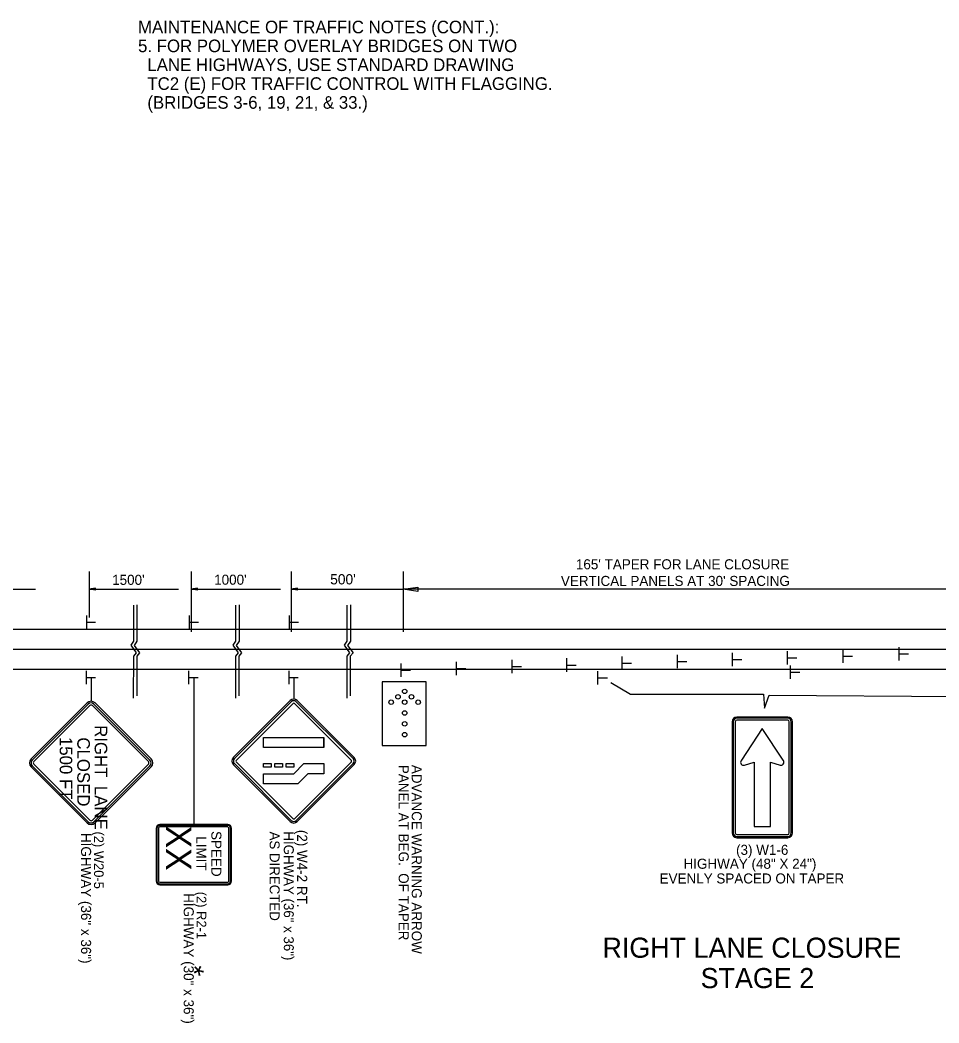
# Model space of a CAD drawing. Extents: x 1930579 to 1937521, y 596183 to 597599.
# Drawn here: x 1935656 to 1936204, y 596928 to 597526 of the extents above; entities that cross this region are included whole.
import ezdxf

# ---------------------------------------------------------------- set-up
doc = ezdxf.new("R2010")
doc.units = 0
for name, color, linetype in [('Default', 7, 'Continuous'), ('P_TC_Signs_Permanent', 7, 'Continuous'), ('P_TC_Signs_Temporary', 7, 'Continuous'), ('R_Annotation', 7, 'Continuous')]:
    doc.layers.add(name, color=color, linetype=linetype)

msp = doc.modelspace()

# ---------------------------------------------------------------- linework, layer by layer
at = {"layer": 'Default'}
for p, q in [((1935696.74, 597197.04), (1935696.74, 597169.66)), ((1935757.62, 597197.04), (1935757.62, 597161.13)), ((1935817.31, 597197.04), (1935817.31, 597161.13)), ((1935884.09, 597197.04), (1935884.09, 597161.13)), ((1935611.55, 597186.51), (1935664.78, 597186.51)), ((1935700.57, 597187.09), (1935696.74, 597186.51)), ((1935696.74, 597186.51), (1935749.97, 597186.51)), ((1935700.57, 597185.94), (1935696.74, 597186.51)), ((1935700.57, 597186.99), (1935697.38, 597186.51)), ((1935700.57, 597186.03), (1935697.38, 597186.51)), ((1935700.57, 597186.89), (1935698.04, 597186.51)), ((1935700.57, 597186.13), (1935698.04, 597186.51)), ((1935700.57, 597186.8), (1935698.67, 597186.51)), ((1935700.57, 597186.23), (1935698.67, 597186.51)), ((1935700.57, 597186.7), (1935699.32, 597186.51)), ((1935700.57, 597186.33), (1935699.32, 597186.51)), ((1935700.57, 597186.6), (1935699.96, 597186.51)), ((1935700.57, 597186.42), (1935699.96, 597186.51)), ((1935700.57, 597185.94), (1935700.57, 597187.09)), ((1935761.45, 597187.09), (1935757.62, 597186.51)), ((1935757.62, 597186.51), (1935810.86, 597186.51)), ((1935761.45, 597185.94), (1935757.62, 597186.51)), ((1935761.45, 597186.99), (1935758.26, 597186.51)), ((1935761.45, 597186.03), (1935758.26, 597186.51)), ((1935761.45, 597186.89), (1935758.92, 597186.51)), ((1935761.45, 597186.13), (1935758.92, 597186.51)), ((1935761.45, 597186.8), (1935759.56, 597186.51)), ((1935761.45, 597186.23), (1935759.56, 597186.51)), ((1935761.45, 597186.7), (1935760.21, 597186.51)), ((1935761.45, 597186.33), (1935760.21, 597186.51)), ((1935761.45, 597186.6), (1935760.85, 597186.51)), ((1935761.45, 597186.42), (1935760.85, 597186.51)), ((1935761.45, 597185.94), (1935761.45, 597187.09)), ((1935821.13, 597187.09), (1935817.31, 597186.51)), ((1935817.31, 597186.51), (1935884.09, 597186.51)), ((1935821.13, 597185.94), (1935817.31, 597186.51)), ((1935821.13, 597186.99), (1935817.95, 597186.51)), ((1935821.13, 597186.03), (1935817.95, 597186.51)), ((1935821.13, 597186.89), (1935818.6, 597186.51)), ((1935821.13, 597186.13), (1935818.6, 597186.51)), ((1935821.13, 597186.8), (1935819.24, 597186.51)), ((1935821.13, 597186.23), (1935819.24, 597186.51)), ((1935821.13, 597186.7), (1935819.89, 597186.51)), ((1935821.13, 597186.33), (1935819.89, 597186.51)), ((1935821.13, 597186.6), (1935820.53, 597186.51)), ((1935821.13, 597186.42), (1935820.53, 597186.51)), ((1935821.13, 597185.94), (1935821.13, 597187.09)), ((1935884.09, 597186.51), (1935892.95, 597187.84)), ((1936251.3, 597186.51), (1935884.09, 597186.51)), ((1935892.95, 597185.18), (1935884.09, 597186.51)), ((1935892.95, 597187.84), (1935892.95, 597185.18)), ((1935695.06, 597170.87), (1935695.06, 597162.89)), ((1935695.18, 597166.9), (1935700.62, 597166.9)), ((1935756.34, 597170.87), (1935756.34, 597162.89)), ((1935756.46, 597166.9), (1935761.9, 597166.9)), ((1935816.02, 597170.87), (1935816.02, 597162.89)), ((1935816.13, 597166.9), (1935821.58, 597166.9)), ((1936503.04, 597162.55), (1935188.53, 597162.55)), ((1936503.04, 597150.55), (1935188.53, 597150.55)), ((1936080.66, 597140.66), (1936080.66, 597148.64)), ((1936113.5, 597141.57), (1936113.5, 597149.55)), ((1936146.65, 597142.67), (1936146.65, 597150.65)), ((1936180.12, 597143.96), (1936180.12, 597151.94)), ((1935915.88, 597135.25), (1935915.88, 597143.23)), ((1935949.18, 597136.49), (1935949.18, 597144.46)), ((1935981.84, 597137.34), (1935981.84, 597145.32)), ((1936014.83, 597138.38), (1936014.83, 597146.36)), ((1936047.81, 597139.43), (1936047.81, 597147.41)), ((1936047.93, 597143.4), (1936053.38, 597143.4)), ((1936080.78, 597144.63), (1936086.23, 597144.63)), ((1936113.61, 597145.53), (1936119.06, 597145.53)), ((1936146.77, 597146.64), (1936152.21, 597146.64)), ((1936180.24, 597147.93), (1936185.69, 597147.93)), ((1936503.04, 597138.55), (1935188.53, 597138.55)), ((1935695.06, 597129.89), (1935695.06, 597137.87)), ((1935756.31, 597129.89), (1935756.31, 597137.87)), ((1935816, 597129.89), (1935816, 597137.87)), ((1935882.89, 597134.21), (1935882.89, 597142.18)), ((1935883.01, 597138.17), (1935888.46, 597138.17)), ((1935915.99, 597139.22), (1935921.44, 597139.22)), ((1935949.3, 597140.45), (1935954.75, 597140.45)), ((1935981.96, 597141.31), (1935987.41, 597141.31)), ((1936000.39, 597129.61), (1936000.39, 597137.59)), ((1936014.94, 597142.35), (1936020.39, 597142.35)), ((1936115.35, 597133.1), (1936115.35, 597141.08)), ((1936115.47, 597137.07), (1936120.92, 597137.07)), ((1935695.17, 597133.86), (1935700.62, 597133.86)), ((1935756.43, 597133.86), (1935761.87, 597133.86)), ((1935816.11, 597133.86), (1935821.56, 597133.86)), ((1936000.51, 597133.58), (1936005.96, 597133.58))]:
    msp.add_line(p, q, dxfattribs=at)
for points in [[(1935723.24, 597177.07), (1935723.24, 597155.55), (1935721.58, 597153.08), (1935724.81, 597148.65), (1935723.11, 597146.6), (1935723.1, 597121.58)], [(1935725.28, 597177.27), (1935725.28, 597155.46), (1935723.62, 597152.99), (1935726.86, 597148.56), (1935725.15, 597146.52), (1935725.15, 597123.02)], [(1935784.12, 597177.07), (1935784.12, 597155.55), (1935782.46, 597153.08), (1935785.7, 597148.65), (1935783.99, 597146.6), (1935783.99, 597121.58)], [(1935786.17, 597177.27), (1935786.17, 597155.46), (1935784.5, 597152.99), (1935787.74, 597148.56), (1935786.04, 597146.52), (1935786.03, 597123.02)], [(1935850.58, 597177.07), (1935850.58, 597155.55), (1935848.92, 597153.08), (1935852.15, 597148.65), (1935850.45, 597146.6), (1935850.44, 597121.58)], [(1935852.62, 597177.27), (1935852.62, 597155.46), (1935850.96, 597152.99), (1935854.2, 597148.56), (1935852.49, 597146.52), (1935852.49, 597123.02)]]:
    msp.add_lwpolyline(points, dxfattribs=at)
msp.add_lwpolyline([(1935871.59, 597131.26), (1935871.59, 597093.28), (1935897.86, 597093.28), (1935897.86, 597131.26)], close=True, dxfattribs=at)
for centre in [(1935885.02, 597125.57), (1935876.97, 597119.12), (1935881, 597122.35), (1935885.02, 597119.12), (1935889.05, 597122.35), (1935893.07, 597119.12), (1935885.02, 597112.67), (1935885.02, 597106.22), (1935885.02, 597099.77)]:
    msp.add_circle(centre, 1.34, dxfattribs=at)
at = {"layer": 'P_TC_Signs_Permanent'}
for p, q in [((1935782.77, 597086.11), (1935816.72, 597120.05)), ((1936080.4, 597107.48), (1936080.4, 597041.1)), ((1936081.15, 597107.48), (1936081.15, 597041.1)), ((1936082.27, 597107.48), (1936082.27, 597041.1)), ((1936113.59, 597110.29), (1936083.21, 597110.29)), ((1936113.59, 597109.54), (1936083.21, 597109.54)), ((1936113.59, 597108.41), (1936083.21, 597108.41)), ((1936114.52, 597041.1), (1936114.52, 597107.48)), ((1936115.65, 597041.1), (1936115.65, 597107.48)), ((1936116.4, 597041.1), (1936116.4, 597107.48)), ((1935836.84, 597092.03), (1935836.84, 597098.03)), ((1935816.72, 597047.93), (1935782.77, 597081.87)), ((1935854.9, 597081.87), (1935820.96, 597047.93)), ((1935736.65, 597043.94), (1935736.65, 597012.44)), ((1935737.21, 597043.94), (1935737.21, 597012.44)), ((1935738.15, 597043.94), (1935738.15, 597012.44)), ((1935779.4, 597046.19), (1935738.9, 597046.19)), ((1935779.4, 597045.63), (1935738.9, 597045.63)), ((1935779.4, 597044.69), (1935738.9, 597044.69)), ((1935780.15, 597012.44), (1935780.15, 597043.94)), ((1935781.09, 597012.44), (1935781.09, 597043.94)), ((1935781.65, 597012.44), (1935781.65, 597043.94)), ((1936083.21, 597040.16), (1936113.59, 597040.16)), ((1936083.21, 597039.04), (1936113.59, 597039.04)), ((1936083.21, 597038.29), (1936113.59, 597038.29)), ((1935738.9, 597011.69), (1935779.4, 597011.69)), ((1935738.9, 597010.75), (1935779.4, 597010.75)), ((1935738.9, 597010.19), (1935779.4, 597010.19))]:
    msp.add_line(p, q, dxfattribs=at)
for points in [[(1935817.35, 597119.42), (1935783.41, 597085.47)], [(1935854.26, 597085.47), (1935820.32, 597119.42)], [(1935820.96, 597120.05), (1935837.93, 597103.08), (1935854.9, 597086.11)], [(1935784.47, 597084.41), (1935818.41, 597118.35)], [(1935819.26, 597118.35), (1935853.2, 597084.41)], [(1936110.84, 597084.55), (1936098.4, 597103.54), (1936085.99, 597084.54)], [(1935818.41, 597049.62), (1935784.47, 597083.56)], [(1935853.2, 597083.56), (1935819.26, 597049.62)], [(1936087.76, 597081.59), (1936093.52, 597083.31), (1936093.52, 597045.04), (1936103.27, 597045.04), (1936103.27, 597083.31), (1936109.02, 597081.55)], [(1935783.41, 597082.5), (1935817.35, 597048.56)], [(1935820.32, 597048.56), (1935854.26, 597082.5)]]:
    msp.add_lwpolyline(points, dxfattribs=at)
for points in [[(1935800.84, 597092.03), (1935800.84, 597098.03), (1935836.84, 597098.03), (1935836.84, 597092.03)], [(1935800.84, 597080.39), (1935800.84, 597082.49), (1935805.34, 597082.49), (1935805.34, 597080.39)], [(1935800.84, 597070.49), (1935800.84, 597076.49), (1935818.84, 597076.49), (1935824.84, 597082.49), (1935836.84, 597082.49), (1935836.84, 597076.49), (1935827.32, 597076.49), (1935821.32, 597070.49)], [(1935807.59, 597080.39), (1935807.59, 597082.49), (1935812.09, 597082.49), (1935812.09, 597080.39)], [(1935814.34, 597080.39), (1935814.34, 597082.49), (1935818.84, 597082.49), (1935818.84, 597080.39)]]:
    msp.add_lwpolyline(points, close=True, dxfattribs=at)
for centre, radius, start, end in [((1935818.84, 597117.93), 3, 45, 135), ((1935818.84, 597117.93), 2.1, 45, 135), ((1935818.84, 597117.93), 0.6, 45, 135), ((1936083.21, 597107.48), 2.81, 90, 180), ((1936083.21, 597107.48), 2.06, 90, 180), ((1936083.21, 597107.48), 0.938, 90, 180), ((1936113.59, 597107.48), 2.81, 360, 90), ((1936113.59, 597107.48), 2.06, 360, 90), ((1936113.59, 597107.48), 0.938, 360, 90), ((1935784.9, 597083.99), 3, 135, 225), ((1935784.9, 597083.99), 2.1, 135, 225), ((1935784.9, 597083.99), 0.6, 135, 225), ((1935852.78, 597083.99), 0.6, 315, 45), ((1935852.78, 597083.99), 2.1, 315, 45), ((1935852.78, 597083.99), 3, 315, 45), ((1936087.28, 597083.28), 1.76, 146.59943, 285.96908), ((1936023.19, 597125.54), 75, 326.59943, 326.85697), ((1936109.52, 597083.28), 1.8, 254.03093, 33.47548), ((1936173.58, 597125.64), 75, 213.2286, 213.47548), ((1935818.84, 597050.05), 3, 225, 315), ((1935818.84, 597050.05), 2.1, 225, 315), ((1935818.84, 597050.05), 0.6, 225, 315), ((1935738.9, 597043.94), 2.25, 90, 180), ((1935738.9, 597043.94), 1.69, 90, 180), ((1935738.9, 597043.94), 0.75, 90, 180), ((1935779.4, 597043.94), 2.25, 360, 90), ((1935779.4, 597043.94), 1.69, 360, 90), ((1935779.4, 597043.94), 0.75, 360, 90), ((1936083.21, 597041.1), 2.81, 180, 270), ((1936083.21, 597041.1), 2.06, 180, 270), ((1936083.21, 597041.1), 0.937, 180, 270), ((1936113.59, 597041.1), 2.81, 270, 360), ((1936113.59, 597041.1), 2.06, 270, 360), ((1936113.59, 597041.1), 0.938, 270, 360), ((1935738.9, 597012.44), 2.25, 180, 270), ((1935738.9, 597012.44), 1.69, 180, 270), ((1935738.9, 597012.44), 0.75, 180, 270), ((1935779.4, 597012.44), 2.25, 270, 360), ((1935779.4, 597012.44), 1.69, 270, 360), ((1935779.4, 597012.44), 0.75, 270, 360)]:
    msp.add_arc(centre, radius, start, end, dxfattribs=at)
at = {"layer": 'P_TC_Signs_Temporary'}
for p, q in [((1935662.1, 597085.29), (1935695.51, 597118.71)), ((1935700.28, 597118.71), (1935733.7, 597085.29)), ((1935662.76, 597084.63), (1935696.17, 597118.04)), ((1935663.69, 597083.7), (1935697.1, 597117.11)), ((1935698.69, 597117.11), (1935732.1, 597083.7)), ((1935699.62, 597118.04), (1935733.03, 597084.63)), ((1935695.51, 597047.11), (1935662.1, 597080.52)), ((1935696.17, 597047.77), (1935662.76, 597081.18)), ((1935697.1, 597048.7), (1935663.69, 597082.11)), ((1935732.1, 597082.11), (1935698.69, 597048.7)), ((1935733.03, 597081.18), (1935699.62, 597047.77)), ((1935733.7, 597080.52), (1935700.28, 597047.11))]:
    msp.add_line(p, q, dxfattribs=at)
for centre, radius, start, end in [((1935697.9, 597116.32), 3.37, 45, 135), ((1935697.9, 597116.32), 2.44, 45, 135), ((1935697.9, 597116.32), 1.12, 45, 135), ((1935664.49, 597082.91), 3.37, 135, 225), ((1935664.49, 597082.91), 2.44, 135, 225), ((1935664.49, 597082.91), 1.13, 135, 225), ((1935731.31, 597082.91), 1.13, 315, 45), ((1935731.31, 597082.91), 2.44, 315, 45), ((1935731.31, 597082.91), 3.38, 315, 45), ((1935697.9, 597049.5), 3.38, 225, 315), ((1935697.9, 597049.5), 2.44, 225, 315), ((1935697.9, 597049.5), 1.12, 225, 315)]:
    msp.add_arc(centre, radius, start, end, dxfattribs=at)
at = {"layer": 'R_Annotation'}
for p, q in [((1935697.9, 597133.86), (1935697.9, 597119.69)), ((1935759.15, 597133.86), (1935759.15, 597046.19)), ((1935818.84, 597133.86), (1935818.84, 597120.93))]:
    msp.add_line(p, q, dxfattribs=at)
msp.add_lwpolyline([(1936008.07, 597130.97), (1936019.88, 597124.02), (1936099.08, 597124.02), (1936099.78, 597115.67), (1936102.56, 597123.32), (1936215.81, 597122.63), (1936229.01, 597134.45)], dxfattribs=at)

# ---------------------------------------------------------------- texts
at = {"layer": 'Default'}
for s, height, p in [("165' TAPER FOR LANE CLOSURE", 5.9999, (1935987.19, 597198.42)), ("1500'", 6, (1935710.46, 597189.15)), ("1000'", 6, (1935771.34, 597189.23)), ("500'", 6.12, (1935840.6, 597189.42)), ("VERTICAL PANELS AT 30' SPACING", 5.9999, (1935978.26, 597188.49)), ('RIGHT LANE CLOSURE', 12, (1936003.05, 596966.66)), ('STAGE 2', 12, (1936061.63, 596948.54))]:
    msp.add_text(s, height=height, rotation=360, dxfattribs=at).set_placement(p)
at = {"layer": 'P_TC_Signs_Permanent'}
for s, height, p in [('XX', 15, (1935742.65, 597045.49)), ('SPEED', 6, (1935769.65, 597042.26)), ('LIMIT', 6, (1935760.65, 597039.17))]:
    msp.add_text(s, height=height, rotation=270, dxfattribs=at).set_placement(p)
at = {"layer": 'P_TC_Signs_Temporary'}
for s, p in [('RIGHT\u2002LANE', (1935700.02, 597105.43)), ('1500 FT', (1935679.15, 597098.43)), ('CLOSED', (1935689.65, 597098.16))]:
    msp.add_text(s, height=7.5, rotation=270, dxfattribs=at).set_placement(p)
at = {"layer": 'R_Annotation'}
for s, height, rotation, p in [('MAINTENANCE OF TRAFFIC NOTES (CONT.): ', 7.5, 360, (1935725.9, 597518.22)), ('5. FOR POLYMER OVERLAY BRIDGES ON TWO', 7.5, 360, (1935725.9, 597506.97)), ('  LANE HIGHWAYS, USE STANDARD DRAWING', 7.5, 360, (1935725.9, 597495.72)), ('  TC2 (E) FOR TRAFFIC CONTROL WITH FLAGGING.  ', 7.5, 360, (1935725.9, 597484.47)), ('  (BRIDGES 3-6, 19, 21, & 33.)', 7.5, 360, (1935725.9, 597473.22)), ('PANEL AT BEG.  OF TAPER', 6, 270, (1935881.44, 597081.75)), ('ADVANCE WARNING ARROW', 6, 270, (1935889.23, 597081.75)), ('(2) W20-5', 5.76, 270, (1935699.63, 597041.99)), ('AS DIRECTED ', 5.9246, 270, (1935804.48, 597041.94)), ('HIGHWAY (36" x 36")', 5.9246, 270, (1935812.91, 597042.05)), ('(2) W4-2 RT.', 6, 270, (1935820.84, 597042.96)), ('HIGHWAY (36" x 36")', 6, 270, (1935691.9, 597041.12)), ('(3) W1-6', 6, 0.00754, (1936082.78, 597028.05)), ('HIGHWAY (48" X 24")', 6, 0.00754, (1936051.44, 597019.75)), ('EVENLY SPACED ON TAPER', 6, 0.00754, (1936037.15, 597010.96)), ('(2) R2-1', 5.76, 270, (1935760.88, 597006.06)), ('HIGHWAY (30" x 36")', 6, 270, (1935753.15, 597005.19)), ('*', 12, 45, (1935766.03, 596950.54))]:
    msp.add_text(s, height=height, rotation=rotation, dxfattribs=at).set_placement(p)

doc.saveas('drawing.dxf')
